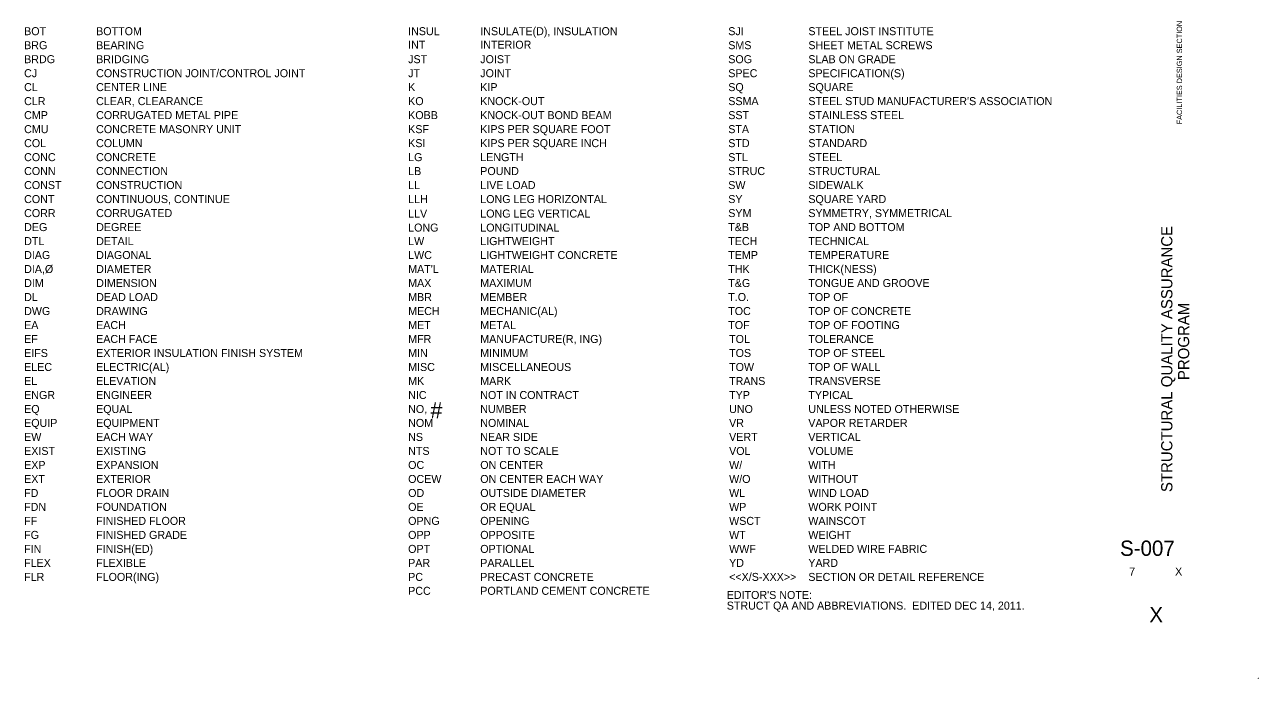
# Model space of a CAD drawing. Extents: x 2632118 to 2632142.4, y 1706724.1 to 1706788.4.
# Drawn here: x 2632126.31 to 2632139.16, y 1706724.07 to 1706730.88 of the extents above; entities that cross this region are included whole.
import ezdxf

# ---------------------------------------------------------------- set-up
doc = ezdxf.new("R2010")
doc.units = 0
doc.layers.add('S-ANNO-TEXT', color=7, linetype='Continuous')

msp = doc.modelspace()

# ---------------------------------------------------------------- linework, layer by layer
at = {"layer": 'S-ANNO-TEXT'}
msp.add_circle((2632139.157, 1706724.068), 0.000134, dxfattribs=at)

# ---------------------------------------------------------------- texts
for s, height, p in [('BOT', 0.0833, (2632126.302, 1706730.771)), ('BOTTOM', 0.0833, (2632127.052, 1706730.771)), ('INSUL', 0.0833, (2632130.302, 1706730.771)), ('INSULATE(D), INSULATION', 0.08333, (2632131.053, 1706730.771)), ('SJI', 0.0833, (2632133.636, 1706730.771)), ('STEEL JOIST INSTITUTE', 0.08333, (2632134.47, 1706730.771)), ('BRG', 0.0833, (2632126.302, 1706730.625)), ('BEARING', 0.0833, (2632127.052, 1706730.625)), ('INT', 0.0833, (2632130.302, 1706730.63)), ('INTERIOR', 0.0833, (2632131.053, 1706730.63)), ('SMS', 0.0833, (2632133.636, 1706730.625)), ('SHEET METAL SCREWS', 0.08333, (2632134.47, 1706730.625)), ('BRDG', 0.0833, (2632126.302, 1706730.479)), ('BRIDGING', 0.0833, (2632127.052, 1706730.479)), ('JST', 0.0833, (2632130.302, 1706730.479)), ('JOIST', 0.0833, (2632131.053, 1706730.479)), ('SOG', 0.0833, (2632133.636, 1706730.479)), ('SLAB ON GRADE', 0.08333, (2632134.47, 1706730.479)), ('CJ', 0.0833, (2632126.302, 1706730.333)), ('CONSTRUCTION JOINT/CONTROL JOINT', 0.08333, (2632127.052, 1706730.333)), ('JT', 0.0833, (2632130.302, 1706730.333)), ('JOINT', 0.0833, (2632131.053, 1706730.333)), ('SPEC', 0.0833, (2632133.636, 1706730.333)), ('SPECIFICATION(S)', 0.08333, (2632134.47, 1706730.333)), ('CL', 0.0833, (2632126.302, 1706730.188)), ('CENTER LINE', 0.08333, (2632127.052, 1706730.188)), ('K', 0.0833, (2632130.302, 1706730.188)), ('KIP', 0.0833, (2632131.053, 1706730.188)), ('SQ', 0.0833, (2632133.636, 1706730.188)), ('SQUARE', 0.0833, (2632134.47, 1706730.188)), ('CLR', 0.0833, (2632126.302, 1706730.042)), ('CLEAR, CLEARANCE', 0.08333, (2632127.052, 1706730.042)), ('KO', 0.0833, (2632130.302, 1706730.042)), ('KNOCK-OUT', 0.0833, (2632131.053, 1706730.042)), ('SSMA', 0.0833, (2632133.636, 1706730.042)), ("STEEL STUD MANUFACTURER'S ASSOCIATION", 0.08333, (2632134.47, 1706730.042)), ('CMP', 0.0833, (2632126.302, 1706729.896)), ('CORRUGATED METAL PIPE', 0.08333, (2632127.052, 1706729.896)), ('KOBB', 0.0833, (2632130.302, 1706729.896)), ('KNOCK-OUT BOND BEAM', 0.08333, (2632131.053, 1706729.896)), ('SST', 0.0833, (2632133.636, 1706729.896)), ('STAINLESS STEEL', 0.08333, (2632134.47, 1706729.896)), ('CMU', 0.0833, (2632126.302, 1706729.75)), ('CONCRETE MASONRY UNIT', 0.08333, (2632127.052, 1706729.75)), ('KSF', 0.0833, (2632130.302, 1706729.75)), ('KIPS PER SQUARE FOOT', 0.08333, (2632131.053, 1706729.75)), ('STA', 0.0833, (2632133.636, 1706729.75)), ('STATION', 0.0833, (2632134.47, 1706729.75)), ('COL', 0.0833, (2632126.302, 1706729.604)), ('COLUMN', 0.0833, (2632127.052, 1706729.604)), ('KSI', 0.0833, (2632130.302, 1706729.604)), ('KIPS PER SQUARE INCH', 0.08333, (2632131.053, 1706729.604)), ('STD', 0.0833, (2632133.636, 1706729.604)), ('STANDARD', 0.0833, (2632134.47, 1706729.604)), ('CONC', 0.0833, (2632126.302, 1706729.458)), ('CONCRETE', 0.0833, (2632127.052, 1706729.458)), ('LG', 0.0833, (2632130.302, 1706729.458)), ('LENGTH', 0.0833, (2632131.053, 1706729.458)), ('STL', 0.0833, (2632133.636, 1706729.458)), ('STEEL', 0.0833, (2632134.47, 1706729.458)), ('CONN', 0.0833, (2632126.302, 1706729.313)), ('CONNECTION', 0.0833, (2632127.052, 1706729.313)), ('LB', 0.0833, (2632130.302, 1706729.313)), ('POUND', 0.0833, (2632131.053, 1706729.313)), ('STRUC', 0.0833, (2632133.636, 1706729.313)), ('STRUCTURAL', 0.0833, (2632134.47, 1706729.313)), ('CONST', 0.0833, (2632126.302, 1706729.167)), ('CONSTRUCTION', 0.08333, (2632127.052, 1706729.167)), ('LL', 0.0833, (2632130.302, 1706729.167)), ('LIVE LOAD', 0.0833, (2632131.053, 1706729.167)), ('SW', 0.0833, (2632133.636, 1706729.167)), ('SIDEWALK', 0.0833, (2632134.47, 1706729.167)), ('CONT', 0.0833, (2632126.302, 1706729.021)), ('CONTINUOUS, CONTINUE', 0.08333, (2632127.052, 1706729.021)), ('LLH', 0.0833, (2632130.302, 1706729.021)), ('LONG LEG HORIZONTAL', 0.08333, (2632131.053, 1706729.021)), ('SY', 0.0833, (2632133.636, 1706729.021)), ('SQUARE YARD', 0.08333, (2632134.47, 1706729.021)), ('CORR', 0.0833, (2632126.302, 1706728.875)), ('CORRUGATED', 0.0833, (2632127.052, 1706728.875)), ('LLV', 0.0833, (2632130.302, 1706728.87)), ('LONG LEG VERTICAL', 0.08333, (2632131.053, 1706728.87)), ('SYM', 0.0833, (2632133.636, 1706728.875)), ('SYMMETRY, SYMMETRICAL', 0.08333, (2632134.47, 1706728.875)), ('DEG', 0.0833, (2632126.302, 1706728.729)), ('DEGREE', 0.0833, (2632127.052, 1706728.729)), ('LONG', 0.0833, (2632130.302, 1706728.724)), ('LONGITUDINAL', 0.08333, (2632131.053, 1706728.724)), ('T&B', 0.0833, (2632133.636, 1706728.729)), ('TOP AND BOTTOM', 0.08333, (2632134.47, 1706728.729)), ('DTL', 0.0833, (2632126.302, 1706728.583)), ('DETAIL', 0.0833, (2632127.052, 1706728.583)), ('LW', 0.0833, (2632130.302, 1706728.583)), ('LIGHTWEIGHT', 0.08333, (2632131.053, 1706728.583)), ('TECH', 0.0833, (2632133.636, 1706728.583)), ('TECHNICAL', 0.0833, (2632134.47, 1706728.583)), ('DIAG', 0.0833, (2632126.302, 1706728.438)), ('DIAGONAL', 0.0833, (2632127.052, 1706728.438)), ('LWC', 0.0833, (2632130.302, 1706728.438)), ('LIGHTWEIGHT CONCRETE', 0.08333, (2632131.053, 1706728.438)), ('TEMP', 0.0833, (2632133.636, 1706728.438)), ('TEMPERATURE', 0.08333, (2632134.47, 1706728.438)), ('DIA,%%C', 0.0833, (2632126.302, 1706728.292)), ('DIAMETER', 0.0833, (2632127.052, 1706728.292)), ("MAT'L", 0.0833, (2632130.302, 1706728.292)), ('MATERIAL', 0.0833, (2632131.053, 1706728.292)), ('THK', 0.0833, (2632133.636, 1706728.292)), ('THICK(NESS)', 0.08333, (2632134.47, 1706728.292)), ('DIM', 0.0833, (2632126.302, 1706728.146)), ('DIMENSION', 0.0833, (2632127.052, 1706728.146)), ('MAX', 0.0833, (2632130.302, 1706728.146)), ('MAXIMUM', 0.0833, (2632131.053, 1706728.146)), ('T&G', 0.0834, (2632133.636, 1706728.146)), ('TONGUE AND GROOVE', 0.08336, (2632134.47, 1706728.146)), ('DL', 0.0833, (2632126.302, 1706728)), ('DEAD LOAD', 0.0833, (2632127.052, 1706728)), ('MBR', 0.0833, (2632130.302, 1706728)), ('MEMBER', 0.0833, (2632131.053, 1706728)), ('T.O.', 0.0833, (2632133.636, 1706728)), ('TOP OF', 0.0833, (2632134.47, 1706728)), ('DWG', 0.0833, (2632126.302, 1706727.854)), ('DRAWING', 0.0833, (2632127.052, 1706727.854)), ('MECH', 0.0833, (2632130.302, 1706727.854)), ('MECHANIC(AL)', 0.08333, (2632131.053, 1706727.854)), ('TOC', 0.0833, (2632133.636, 1706727.854)), ('TOP OF CONCRETE', 0.08333, (2632134.47, 1706727.854)), ('EA', 0.0833, (2632126.302, 1706727.708)), ('EACH', 0.0833, (2632127.052, 1706727.708)), ('MET', 0.0833, (2632130.302, 1706727.708)), ('METAL', 0.0833, (2632131.053, 1706727.708)), ('TOF', 0.0833, (2632133.636, 1706727.708)), ('TOP OF FOOTING', 0.08333, (2632134.47, 1706727.708)), ('EF', 0.0833, (2632126.302, 1706727.563)), ('EACH FACE', 0.0833, (2632127.052, 1706727.563)), ('MFR', 0.0833, (2632130.302, 1706727.563)), ('MANUFACTURE(R, ING)', 0.08333, (2632131.053, 1706727.563)), ('TOL', 0.0833, (2632133.645, 1706727.563)), ('TOLERANCE', 0.0833, (2632134.47, 1706727.563)), ('EIFS', 0.0833, (2632126.302, 1706727.417)), ('EXTERIOR INSULATION FINISH SYSTEM', 0.08333, (2632127.052, 1706727.417)), ('MIN', 0.0833, (2632130.302, 1706727.417)), ('MINIMUM', 0.0833, (2632131.053, 1706727.417)), ('TOS', 0.0833, (2632133.645, 1706727.417)), ('TOP OF STEEL', 0.08333, (2632134.47, 1706727.417)), ('ELEC', 0.0833, (2632126.302, 1706727.271)), ('ELECTRIC(AL)', 0.08333, (2632127.052, 1706727.271)), ('MISC', 0.0833, (2632130.302, 1706727.271)), ('MISCELLANEOUS', 0.08333, (2632131.053, 1706727.271)), ('TOW', 0.0833, (2632133.645, 1706727.271)), ('TOP OF WALL', 0.08333, (2632134.47, 1706727.271)), ('EL', 0.0833, (2632126.302, 1706727.125)), ('ELEVATION', 0.0833, (2632127.052, 1706727.125)), ('MK', 0.0833, (2632130.302, 1706727.125)), ('MARK', 0.0833, (2632131.053, 1706727.125)), ('TRANS', 0.0833, (2632133.645, 1706727.125)), ('TRANSVERSE', 0.0833, (2632134.47, 1706727.125)), ('ENGR', 0.0833, (2632126.302, 1706726.979)), ('ENGINEER', 0.0833, (2632127.052, 1706726.979)), ('NIC', 0.0833, (2632130.302, 1706726.979)), ('NOT IN CONTRACT', 0.08333, (2632131.053, 1706726.979)), ('TYP', 0.0833, (2632133.645, 1706726.979)), ('TYPICAL', 0.0833, (2632134.47, 1706726.979)), ('EQ', 0.0833, (2632126.302, 1706726.833)), ('EQUAL', 0.0833, (2632127.052, 1706726.833)), ('NO,', 0.0833, (2632130.302, 1706726.833)), ('#', 0.167, (2632130.534, 1706726.778)), ('NUMBER', 0.0833, (2632131.053, 1706726.833)), ('UNO', 0.0833, (2632133.645, 1706726.833)), ('UNLESS NOTED OTHERWISE', 0.08333, (2632134.47, 1706726.833)), ('EQUIP', 0.0833, (2632126.302, 1706726.688)), ('EQUIPMENT', 0.0833, (2632127.052, 1706726.688)), ('NOM', 0.0833, (2632130.302, 1706726.688)), ('NOMINAL', 0.0833, (2632131.053, 1706726.688)), ('VR', 0.0833, (2632133.645, 1706726.688)), ('VAPOR RETARDER', 0.08333, (2632134.47, 1706726.688)), ('EW', 0.0833, (2632126.302, 1706726.542)), ('EACH WAY', 0.0833, (2632127.052, 1706726.542)), ('NS', 0.0833, (2632130.302, 1706726.542)), ('NEAR SIDE', 0.0833, (2632131.053, 1706726.542)), ('VERT', 0.0833, (2632133.645, 1706726.542)), ('VERTICAL', 0.0833, (2632134.47, 1706726.542)), ('EXIST', 0.0833, (2632126.302, 1706726.396)), ('EXISTING', 0.0833, (2632127.052, 1706726.396)), ('NTS', 0.0833, (2632130.302, 1706726.396)), ('NOT TO SCALE', 0.08333, (2632131.053, 1706726.396)), ('VOL', 0.0833, (2632133.645, 1706726.396)), ('VOLUME', 0.0833, (2632134.47, 1706726.396)), ('EXP', 0.0833, (2632126.302, 1706726.25)), ('EXPANSION', 0.0833, (2632127.052, 1706726.25)), ('OC', 0.0833, (2632130.302, 1706726.25)), ('ON CENTER', 0.0833, (2632131.053, 1706726.25)), ('W/', 0.0833, (2632133.645, 1706726.25)), ('WITH', 0.0833, (2632134.47, 1706726.25)), ('EXT', 0.0833, (2632126.302, 1706726.104)), ('EXTERIOR', 0.0833, (2632127.052, 1706726.104)), ('OCEW', 0.0833, (2632130.302, 1706726.104)), ('ON CENTER EACH WAY', 0.08333, (2632131.053, 1706726.104)), ('W/O', 0.0833, (2632133.645, 1706726.104)), ('WITHOUT', 0.0833, (2632134.47, 1706726.104)), ('FD', 0.0833, (2632126.302, 1706725.958)), ('FLOOR DRAIN', 0.08333, (2632127.052, 1706725.958)), ('OD', 0.0833, (2632130.302, 1706725.958)), ('OUTSIDE DIAMETER', 0.08333, (2632131.053, 1706725.958)), ('WL', 0.0833, (2632133.645, 1706725.958)), ('WIND LOAD', 0.0833, (2632134.47, 1706725.958)), ('FDN', 0.0833, (2632126.302, 1706725.813)), ('FOUNDATION', 0.0833, (2632127.052, 1706725.813)), ('OE', 0.0833, (2632130.302, 1706725.813)), ('OR EQUAL', 0.0833, (2632131.053, 1706725.813)), ('WP', 0.0833, (2632133.645, 1706725.813)), ('WORK POINT', 0.0833, (2632134.47, 1706725.813)), ('FF', 0.0833, (2632126.302, 1706725.667)), ('FINISHED FLOOR', 0.08333, (2632127.052, 1706725.667)), ('OPNG', 0.0833, (2632130.302, 1706725.667)), ('OPENING', 0.0833, (2632131.053, 1706725.667)), ('WSCT', 0.0833, (2632133.645, 1706725.667)), ('WAINSCOT', 0.0833, (2632134.47, 1706725.667)), ('FG', 0.0833, (2632126.302, 1706725.521)), ('FINISHED GRADE', 0.08333, (2632127.052, 1706725.521)), ('OPP', 0.0833, (2632130.302, 1706725.521)), ('OPPOSITE', 0.0833, (2632131.053, 1706725.521)), ('WT', 0.0833, (2632133.645, 1706725.521)), ('WEIGHT', 0.0833, (2632134.47, 1706725.521)), ('FIN', 0.0833, (2632126.302, 1706725.375)), ('FINISH(ED)', 0.0833, (2632127.052, 1706725.375)), ('OPT', 0.0833, (2632130.302, 1706725.375)), ('OPTIONAL', 0.0833, (2632131.053, 1706725.375)), ('WWF', 0.0833, (2632133.645, 1706725.375)), ('WELDED WIRE FABRIC', 0.08333, (2632134.47, 1706725.375)), ('S-007', 0.1597, (2632137.717, 1706725.344)), ('FLEX', 0.0833, (2632126.302, 1706725.229)), ('FLEXIBLE', 0.0833, (2632127.052, 1706725.229)), ('PAR', 0.0833, (2632130.302, 1706725.229)), ('PARALLEL', 0.0833, (2632131.053, 1706725.229)), ('YD', 0.0833, (2632133.645, 1706725.229)), ('YARD', 0.0833, (2632134.47, 1706725.229)), ('7', 0.0833, (2632137.812, 1706725.139)), ('X', 0.0833, (2632138.29, 1706725.139)), ('FLR', 0.0833, (2632126.302, 1706725.083)), ('FLOOR(ING)', 0.0833, (2632127.052, 1706725.083)), ('PC', 0.0833, (2632130.302, 1706725.083)), ('PRECAST CONCRETE', 0.08333, (2632131.053, 1706725.083)), ('<<X/S-XXX>>', 0.08333, (2632133.645, 1706725.083)), ('SECTION OR DETAIL REFERENCE', 0.08333, (2632134.47, 1706725.083)), ('PCC', 0.0833, (2632130.302, 1706724.938)), ('PORTLAND CEMENT CONCRETE', 0.08333, (2632131.053, 1706724.938)), ("EDITOR'S NOTE:", 0.08336, (2632133.62, 1706724.895)), ('STRUCT QA AND ABBREVIATIONS.  EDITED DEC 14, 2011.', 0.08336, (2632133.62, 1706724.784)), ('X', 0.16, (2632138.022, 1706724.651))]:
    msp.add_text(s, height=height, dxfattribs=at).set_placement(p)
for s, height, p in [('FACILITIES DESIGN SECTION', 0.05511, (2632138.363, 1706729.842)), ('STRUCTURAL QUALITY ASSURANCE', 0.11667, (2632138.262, 1706726.009)), ('PROGRAM', 0.1167, (2632138.437, 1706727.176))]:
    msp.add_text(s, height=height, rotation=90, dxfattribs=at).set_placement(p)

doc.saveas('drawing.dxf')
